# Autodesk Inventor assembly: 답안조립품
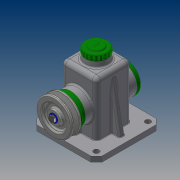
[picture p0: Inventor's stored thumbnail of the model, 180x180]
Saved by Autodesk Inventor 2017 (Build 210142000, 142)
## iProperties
Part Number: 답안조립품
Material: 일반
Document SubType Name: Assembly
Designer: 20
Author: 20
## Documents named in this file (14)
- C:\Users\20\Desktop\470818V1015\답안조립품.iam
- C:\Users\20\Desktop\470818V1015\본체.ipt
- C:\Users\20\Desktop\470818V1015\앞커버.ipt
- C:\Users\20\Desktop\470818V1015\뒤커버.ipt
- C:\Users\20\Desktop\470818V1015\베어링 15 x 35 x 11.ipt
- C:\Users\20\Desktop\470818V1015\멈춤링 15 x 1.ipt
- C:\Users\20\Desktop\470818V1015\축.ipt
- C:\Users\20\Desktop\470818V1015\V-벨트풀리.ipt
- C:\Users\20\Desktop\470818V1015\키 5 x 5 x 14.ipt
- C:\Users\20\Desktop\470818V1015\와셔.ipt
- C:\Users\20\Desktop\470818V1015\볼트 M6 x 12.ipt
- C:\Users\20\Desktop\470818V1015\상부캡.ipt
- C:\Users\20\Desktop\470818V1015\볼트 M4 x 10.ipt
- C:\Users\20\Desktop\470818V1015\오일실 15 25 7.ipt
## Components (1 placed, 1 different names)
1. V-벨트풀리:1 — 플러쉬:1
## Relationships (1: Flush 1)
- 플러쉬:1 [Flush]: V-벨트풀리:1
